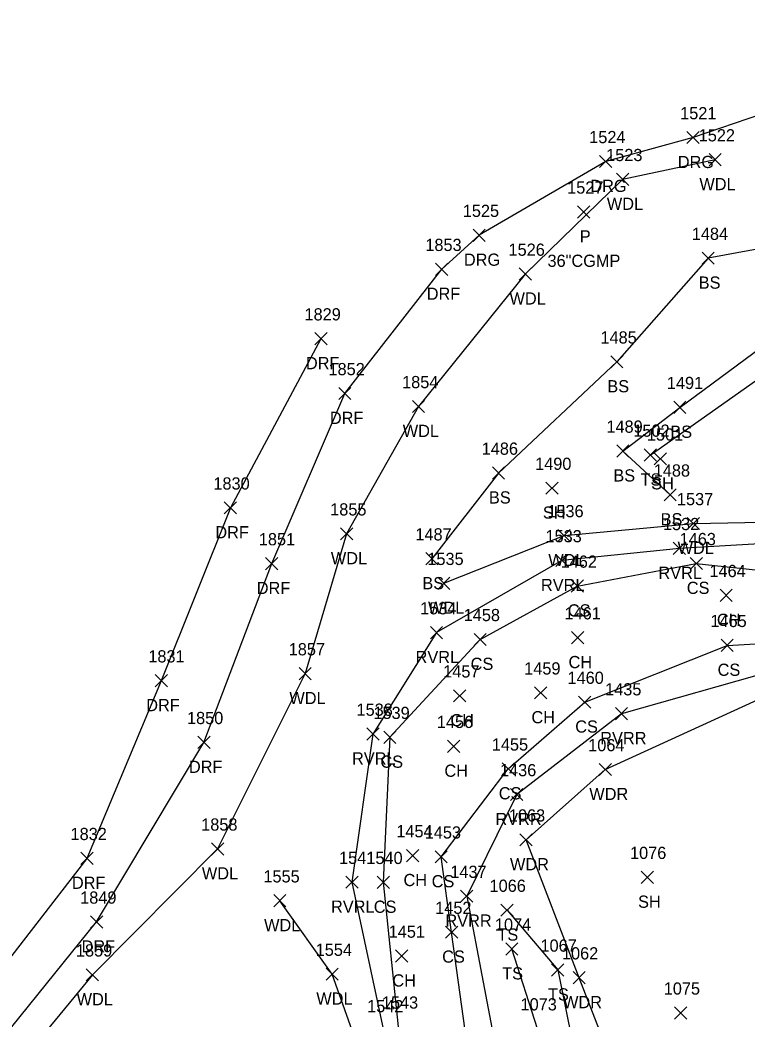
# Model space of a CAD drawing. Extents: x 1621633 to 1624015, y 417863 to 420979.
# Drawn here: x 1621891.2 to 1622010.4, y 418184 to 418348 of the extents above; entities that cross this region are included whole.
import ezdxf

# ---------------------------------------------------------------- set-up
doc = ezdxf.new("R2010")
doc.units = 0
for name, color, linetype in [('D_A', 7, 'Continuous'), ('D_C', 7, 'Continuous'), ('D_I', 7, 'Continuous'), ('D_TIC', 7, 'Continuous'), ('L_A', 7, 'Continuous'), ('L_I', 7, 'Continuous'), ('L_TIC', 7, 'Continuous'), ('LAWA', 7, 'Continuous'), ('LAWE', 7, 'Continuous'), ('LELB', 7, 'Continuous'), ('R_A', 7, 'Continuous'), ('R_I', 7, 'Continuous'), ('R_TIC', 7, 'Continuous'), ('RDF', 7, 'Continuous'), ('RDG', 7, 'Continuous')]:
    doc.layers.add(name, color=color, linetype=linetype)

msp = doc.modelspace()

# ---------------------------------------------------------------- linework, layer by layer
at = {"layer": 'D_TIC'}
for points in [[(1621982.65, 418315.5), (1621984.65, 418317.5)], [(1621984.65, 418315.5), (1621982.65, 418317.5)]]:
    msp.add_lwpolyline(points, dxfattribs=at)
at = {"layer": 'L_TIC'}
for points in [[(1622004.21, 418324.07), (1622006.21, 418326.07)], [(1622006.21, 418324.07), (1622004.21, 418326.07)], [(1621989.04, 418320.84), (1621991.04, 418322.84)], [(1621991.04, 418320.84), (1621989.04, 418322.84)], [(1622003.08, 418307.92), (1622005.08, 418309.92)], [(1622005.08, 418307.92), (1622003.08, 418309.92)], [(1621973.09, 418305.32), (1621975.09, 418307.32)], [(1621975.09, 418305.32), (1621973.09, 418307.32)], [(1621988.1, 418290.93), (1621990.1, 418292.93)], [(1621990.1, 418290.93), (1621988.1, 418292.93)], [(1621955.58, 418283.61), (1621957.58, 418285.61)], [(1621957.58, 418283.61), (1621955.58, 418285.61)], [(1621998.43, 418283.47), (1622000.43, 418285.47)], [(1622000.43, 418283.47), (1621998.43, 418285.47)], [(1621989.09, 418276.31), (1621991.09, 418278.31)], [(1621991.09, 418276.31), (1621989.09, 418278.31)], [(1621993.58, 418275.65), (1621995.58, 418277.65)], [(1621995.58, 418275.65), (1621993.58, 418277.65)], [(1621995.24, 418275.02), (1621997.24, 418277.02)], [(1621997.24, 418275.02), (1621995.24, 418277.02)], [(1621968.69, 418272.7), (1621970.69, 418274.7)], [(1621970.69, 418272.7), (1621968.69, 418274.7)], [(1621977.48, 418270.22), (1621979.48, 418272.22)], [(1621979.48, 418270.22), (1621977.48, 418272.22)], [(1621996.84, 418269.12), (1621998.84, 418271.12)], [(1621998.84, 418269.12), (1621996.84, 418271.12)], [(1622000.65, 418264.43), (1622002.65, 418266.43)], [(1622002.65, 418264.43), (1622000.65, 418266.43)], [(1621943.79, 418262.74), (1621945.79, 418264.74)], [(1621945.79, 418262.74), (1621943.79, 418264.74)], [(1621979.44, 418262.45), (1621981.44, 418264.45)], [(1621981.44, 418262.45), (1621979.44, 418264.45)], [(1621998.35, 418260.34), (1622000.35, 418262.34)], [(1622000.35, 418260.34), (1621998.35, 418262.34)], [(1621957.77, 418258.65), (1621959.77, 418260.65)], [(1621959.77, 418258.65), (1621957.77, 418260.65)], [(1621979.1, 418258.35), (1621981.1, 418260.35)], [(1621981.1, 418258.35), (1621979.1, 418260.35)], [(1622001.13, 418257.88), (1622003.13, 418259.88)], [(1622003.13, 418257.88), (1622001.13, 418259.88)], [(1621959.73, 418254.62), (1621961.73, 418256.62)], [(1621961.73, 418254.62), (1621959.73, 418256.62)], [(1621981.62, 418254.18), (1621983.62, 418256.18)], [(1621983.62, 418254.18), (1621981.62, 418256.18)], [(1622006.02, 418252.64), (1622008.02, 418254.64)], [(1622008.02, 418252.64), (1622006.02, 418254.64)], [(1621958.54, 418246.53), (1621960.54, 418248.53)], [(1621960.54, 418246.53), (1621958.54, 418248.53)], [(1621965.69, 418245.42), (1621967.69, 418247.42)], [(1621967.69, 418245.42), (1621965.69, 418247.42)], [(1621981.69, 418245.71), (1621983.69, 418247.71)], [(1621983.69, 418245.71), (1621981.69, 418247.71)], [(1622006.18, 418244.45), (1622008.18, 418246.45)], [(1622008.18, 418244.45), (1622006.18, 418246.45)], [(1621936.99, 418239.81), (1621938.99, 418241.81)], [(1621938.99, 418239.81), (1621936.99, 418241.81)], [(1621975.61, 418236.67), (1621977.61, 418238.67)], [(1621977.61, 418236.67), (1621975.61, 418238.67)], [(1621962.32, 418236.18), (1621964.32, 418238.18)], [(1621964.32, 418236.18), (1621962.32, 418238.18)], [(1621982.84, 418235.14), (1621984.84, 418237.14)], [(1621984.84, 418235.14), (1621982.84, 418237.14)], [(1621988.87, 418233.25), (1621990.87, 418235.25)], [(1621990.87, 418233.25), (1621988.87, 418235.25)], [(1621948.11, 418229.91), (1621950.11, 418231.91)], [(1621950.11, 418229.91), (1621948.11, 418231.91)], [(1621950.89, 418229.38), (1621952.89, 418231.38)], [(1621952.89, 418229.38), (1621950.89, 418231.38)], [(1621961.34, 418227.9), (1621963.34, 418229.9)], [(1621963.34, 418227.9), (1621961.34, 418229.9)], [(1621970.3, 418224.2), (1621972.3, 418226.2)], [(1621972.3, 418224.2), (1621970.3, 418226.2)], [(1621986.21, 418224.09), (1621988.21, 418226.09)], [(1621988.21, 418224.09), (1621986.21, 418226.09)], [(1621971.68, 418219.99), (1621973.68, 418221.99)], [(1621973.68, 418219.99), (1621971.68, 418221.99)], [(1621973.22, 418212.57), (1621975.22, 418214.57)], [(1621975.22, 418212.57), (1621973.22, 418214.57)], [(1621922.64, 418211.08), (1621924.64, 418213.08)], [(1621924.64, 418211.08), (1621922.64, 418213.08)], [(1621954.63, 418209.98), (1621956.63, 418211.98)], [(1621956.63, 418209.98), (1621954.63, 418211.98)], [(1621959.3, 418209.78), (1621961.3, 418211.78)], [(1621961.3, 418209.78), (1621959.3, 418211.78)], [(1621944.67, 418205.62), (1621946.67, 418207.62)], [(1621946.67, 418205.62), (1621944.67, 418207.62)], [(1621949.81, 418205.6), (1621951.81, 418207.6)], [(1621951.81, 418205.6), (1621949.81, 418207.6)], [(1621993.09, 418206.43), (1621995.09, 418208.43)], [(1621995.09, 418206.43), (1621993.09, 418208.43)], [(1621932.84, 418202.58), (1621934.84, 418204.58)], [(1621934.84, 418202.58), (1621932.84, 418204.58)], [(1621963.49, 418203.33), (1621965.49, 418205.33)], [(1621965.49, 418203.33), (1621963.49, 418205.33)], [(1621970.1, 418201.04), (1621972.1, 418203.04)], [(1621972.1, 418201.04), (1621970.1, 418203.04)], [(1621961.01, 418197.43), (1621963.01, 418199.43)], [(1621963.01, 418197.43), (1621961.01, 418199.43)], [(1621970.89, 418194.68), (1621972.89, 418196.68)], [(1621972.89, 418194.68), (1621970.89, 418196.68)], [(1621952.82, 418193.52), (1621954.82, 418195.52)], [(1621954.82, 418193.52), (1621952.82, 418195.52)], [(1621902.11, 418190.44), (1621904.11, 418192.44)], [(1621904.11, 418190.44), (1621902.11, 418192.44)], [(1621941.42, 418190.54), (1621943.42, 418192.54)], [(1621943.42, 418190.54), (1621941.42, 418192.54)], [(1621978.4, 418191.23), (1621980.4, 418193.23)], [(1621980.4, 418191.23), (1621978.4, 418193.23)], [(1621981.92, 418189.96), (1621983.92, 418191.96)], [(1621983.92, 418189.96), (1621981.92, 418191.96)], [(1621998.57, 418184.19), (1622000.57, 418186.19)], [(1622000.57, 418184.19), (1621998.57, 418186.19)]]:
    msp.add_lwpolyline(points, dxfattribs=at)
at = {"layer": 'LAWA'}
for points in [[(1622005.21, 418325.07), (1621990.04, 418321.84), (1621974.09, 418306.32)], [(1621974.09, 418306.32), (1621956.58, 418284.61)], [(1621956.58, 418284.61), (1621944.79, 418263.74), (1621937.99, 418240.81), (1621923.64, 418212.08), (1621903.11, 418191.44), (1621882.69, 418166.67), (1621873.44, 418154.29), (1621850.99, 418135.57), (1621826.17, 418116.06), (1621804.72, 418096.14), (1621776.82, 418074.39), (1621781.78, 418070.72), (1621808.71, 418078.7), (1621829.62, 418083.56), (1621862.33, 418091.33), (1621892.29, 418098.27), (1621914.93, 418102.81), (1621920.3, 418103.1), (1621927.79, 418103.9), (1621958.83, 418106.15)], [(1621960.73, 418255.62), (1621980.44, 418263.45), (1622001.65, 418265.43)], [(1622001.65, 418265.43), (1622021.3, 418265.82)], [(1622320.21, 418157.08), (1622282.22, 418156.15), (1622251.71, 418155.08), (1622223.6, 418155.09), (1622209.11, 418155.31), (1622180.88, 418152.89), (1622152.12, 418150.87), (1622117.37, 418144.74), (1622094.14, 418141.69), (1622062.96, 418134.28), (1622030.01, 418125.89), (1622002.09, 418113.22), (1622001.94, 418118.19), (1622004.41, 418142.61), (1621992.55, 418166.21), (1621982.92, 418190.96), (1621974.22, 418213.57), (1621987.21, 418225.09), (1622016.71, 418238.58), (1622052.18, 418242.59)], [(1621964.88, 418112.57), (1621960.51, 418127.09), (1621958.47, 418132.3), (1621952.2, 418163.99), (1621942.42, 418191.54), (1621933.84, 418203.58)]]:
    msp.add_lwpolyline(points, dxfattribs=at)
at = {"layer": 'LAWE'}
for points in [[(1622333.17, 418232.98), (1622304.92, 418224.43), (1622278.58, 418222.6), (1622250.59, 418234.06), (1622231.09, 418250.9), (1622207.09, 418257.63), (1622185.14, 418265.61), (1622157.85, 418271.29), (1622128.42, 418279.11), (1622109.18, 418281.03), (1622103.42, 418276.53), (1622081.07, 418269.59), (1622054.89, 418266.85), (1622024.68, 418262.78), (1621999.35, 418261.34), (1621980.1, 418259.35), (1621959.54, 418247.53), (1621949.11, 418230.91), (1621945.67, 418206.62), (1621950.84, 418182.3), (1621958.69, 418157.04), (1621962.92, 418133.77), (1621970.23, 418110.89)], [(1622323.31, 418180.93), (1622300.82, 418170.32), (1622276.31, 418168.44), (1622241.72, 418167.29), (1622221.82, 418173.51), (1622205.88, 418194.82), (1622185.97, 418220.63), (1622162.23, 418235.42), (1622129.82, 418241.7), (1622106.38, 418246.35), (1622101.43, 418250.25), (1622073.09, 418248.58), (1622043.82, 418244.16), (1622014.93, 418241.31), (1621989.87, 418234.25), (1621972.68, 418220.99), (1621964.49, 418204.33), (1621969.88, 418176.14), (1621978.91, 418154.62), (1621984.37, 418139.62), (1621989.94, 418122.86), (1621991.15, 418115.14)]]:
    msp.add_lwpolyline(points, dxfattribs=at)
at = {"layer": 'LELB'}
for points in [[(1622104.98, 418282.3), (1622095.2, 418294.25), (1622098.08, 418303.07), (1622082.32, 418316.41), (1622059.02, 418318.28), (1622035.86, 418314.76), (1622004.08, 418308.92), (1621989.1, 418291.93), (1621969.69, 418273.7), (1621958.77, 418259.65)], [(1621997.84, 418270.12), (1621990.09, 418277.31), (1621999.43, 418284.47), (1622018.11, 418298.26), (1622043.7, 418305.02), (1622071.43, 418306.95), (1622080.52, 418293.1), (1622093.77, 418281.88)], [(1621994.58, 418276.65), (1622013.68, 418290.12), (1622039.52, 418301.76), (1622066, 418303.22), (1622071.17, 418289.62)], [(1621966.69, 418246.42), (1621982.62, 418255.18), (1622002.13, 418258.88), (1622025.63, 418256.38), (1622052.08, 418261.91), (1622065.2, 418262.89), (1622087.25, 418265.4)], [(1621986.07, 418114.57), (1621980.01, 418135.51), (1621971.8, 418158.97), (1621964.78, 418178.35), (1621962.01, 418198.43), (1621960.3, 418210.78), (1621971.3, 418225.2), (1621983.84, 418236.14), (1622007.18, 418245.45), (1622025.65, 418246.51), (1622054.04, 418255.07), (1622065.32, 418256.15)], [(1621951.89, 418230.38), (1621966.69, 418246.42)], [(1621951.89, 418230.38), (1621950.81, 418206.6), (1621953.26, 418182.89), (1621961.47, 418157.62), (1621964.44, 418135.42), (1621972.58, 418110.48)], [(1621971.1, 418202.04), (1621979.4, 418192.23), (1621984.23, 418168.43), (1621996.45, 418147.46), (1621999.49, 418124.25), (1621994.98, 418134.3), (1621984.25, 418161.1), (1621976.08, 418182.6), (1621971.89, 418195.68)]]:
    msp.add_lwpolyline(points, dxfattribs=at)
at = {"layer": 'R_TIC'}
for points in [[(1622000.6, 418327.7), (1622002.6, 418329.7)], [(1622002.6, 418327.7), (1622000.6, 418329.7)], [(1621986.27, 418323.78), (1621988.27, 418325.78)], [(1621988.27, 418323.78), (1621986.27, 418325.78)], [(1621965.53, 418311.68), (1621967.53, 418313.68)], [(1621967.53, 418311.68), (1621965.53, 418313.68)], [(1621959.39, 418306.1), (1621961.39, 418308.1)], [(1621961.39, 418306.1), (1621959.39, 418308.1)], [(1621939.59, 418294.72), (1621941.59, 418296.72)], [(1621941.59, 418294.72), (1621939.59, 418296.72)], [(1621943.51, 418285.74), (1621945.51, 418287.74)], [(1621945.51, 418285.74), (1621943.51, 418287.74)], [(1621924.73, 418266.99), (1621926.73, 418268.99)], [(1621926.73, 418266.99), (1621924.73, 418268.99)], [(1621931.52, 418257.85), (1621933.52, 418259.85)], [(1621933.52, 418257.85), (1621931.52, 418259.85)], [(1621913.41, 418238.65), (1621915.41, 418240.65)], [(1621915.41, 418238.65), (1621913.41, 418240.65)], [(1621920.4, 418228.54), (1621922.4, 418230.54)], [(1621922.4, 418228.54), (1621920.4, 418230.54)], [(1621901.22, 418209.53), (1621903.22, 418211.53)], [(1621903.22, 418209.53), (1621901.22, 418211.53)], [(1621902.81, 418199.1), (1621904.81, 418201.1)], [(1621904.81, 418199.1), (1621902.81, 418201.1)]]:
    msp.add_lwpolyline(points, dxfattribs=at)
at = {"layer": 'RDF'}
for points in [[(1621960.39, 418307.1), (1621966.53, 418312.68)], [(1621776.02, 418061.68), (1621769.52, 418069.9), (1621769.16, 418078.76), (1621780.25, 418093.21), (1621805.38, 418110.92), (1621830.45, 418131.22), (1621857.04, 418151.01), (1621883.03, 418174.44), (1621903.81, 418200.1), (1621921.4, 418229.54), (1621932.52, 418258.85), (1621944.51, 418286.74), (1621960.39, 418307.1)], [(1621940.59, 418295.72), (1621925.73, 418267.99), (1621914.41, 418239.65), (1621902.22, 418210.53), (1621883.89, 418186.91), (1621861.02, 418166.16), (1621838.61, 418146.11), (1621813.95, 418127.94), (1621789.4, 418110.13), (1621762.83, 418096.6), (1621756.07, 418081.78), (1621758.54, 418055.77)]]:
    msp.add_lwpolyline(points, dxfattribs=at)
at = {"layer": 'RDG'}
msp.add_lwpolyline([(1622075.73, 418347.97), (1622049.16, 418344.23), (1622026.25, 418337.1), (1622001.6, 418328.7), (1621987.27, 418324.78), (1621966.53, 418312.68)], dxfattribs=at)

# ---------------------------------------------------------------- texts
at = {"layer": 'D_A'}
msp.add_text('P', height=2, dxfattribs=at).set_placement((1621983.02, 418311.5))
at = {"layer": 'D_C'}
msp.add_text('36"CGMP', height=2, dxfattribs=at).set_placement((1621977.73, 418307.5))
at = {"layer": 'D_I'}
msp.add_text('1527', height=2, dxfattribs=at).set_placement((1621980.95, 418319.5))
at = {"layer": 'L_A'}
for s, p in [('WDL', (1622002.63, 418320.07)), ('WDL', (1621987.46, 418316.84)), ('BS', (1622002.52, 418303.92)), ('WDL', (1621971.5, 418301.32)), ('BS', (1621987.54, 418286.93)), ('WDL', (1621954, 418279.61)), ('BS', (1621997.87, 418279.47)), ('BS', (1621988.53, 418272.31)), ('TS', (1621992.99, 418271.65)), ('SH', (1621994.73, 418271.02)), ('BS', (1621968.13, 418268.7)), ('SH', (1621976.97, 418266.22)), ('BS', (1621996.28, 418265.12)), ('WDL', (1621999.06, 418260.43)), ('WDL', (1621942.21, 418258.74)), ('WDL', (1621977.86, 418258.45)), ('RVRL', (1621995.92, 418256.34)), ('BS', (1621957.21, 418254.65)), ('RVRL', (1621976.66, 418254.35)), ('CS', (1622000.57, 418253.88)), ('WDL', (1621958.14, 418250.62)), ('CS', (1621981.07, 418250.18)), ('CH', (1622005.51, 418248.64)), ('RVRL', (1621956.11, 418242.53)), ('CS', (1621965.13, 418241.42)), ('CH', (1621981.18, 418241.71)), ('CS', (1622005.62, 418240.45)), ('WDL', (1621935.41, 418235.81)), ('CH', (1621961.81, 418232.18)), ('CH', (1621975.1, 418232.67)), ('CS', (1621982.28, 418231.14)), ('RVRR', (1621986.38, 418229.25)), ('RVRL', (1621945.68, 418225.91)), ('CS', (1621950.33, 418225.38)), ('CH', (1621960.83, 418223.9)), ('CS', (1621969.74, 418220.2)), ('WDR', (1621984.58, 418220.09)), ('RVRR', (1621969.2, 418215.99)), ('WDR', (1621971.58, 418208.57)), ('WDL', (1621921.06, 418207.08)), ('CH', (1621954.12, 418205.98)), ('CS', (1621958.74, 418205.78)), ('SH', (1621992.58, 418202.43)), ('RVRL', (1621942.24, 418201.62)), ('CS', (1621949.25, 418201.6)), ('RVRR', (1621961, 418199.33)), ('WDL', (1621931.26, 418198.58)), ('TS', (1621969.51, 418197.04)), ('CS', (1621960.46, 418193.43)), ('TS', (1621970.3, 418190.68)), ('CH', (1621952.3, 418189.52)), ('TS', (1621977.81, 418187.23)), ('WDL', (1621900.53, 418186.44)), ('WDL', (1621939.83, 418186.54)), ('WDR', (1621980.28, 418185.96))]:
    msp.add_text(s, height=2, dxfattribs=at).set_placement(p)
at = {"layer": 'L_I'}
for s, p in [('1522', (1622002.52, 418328.07)), ('1523', (1621987.35, 418324.84)), ('1484', (1622001.39, 418311.92)), ('1526', (1621971.34, 418309.32)), ('1485', (1621986.41, 418294.93)), ('1854', (1621953.89, 418287.61)), ('1491', (1621997.3, 418287.47)), ('1489', (1621987.39, 418280.31)), ('1502', (1621991.8, 418279.65)), ('1501', (1621994.03, 418279.02)), ('1486', (1621966.94, 418276.7)), ('1490', (1621975.7, 418274.22)), ('1488', (1621995.15, 418273.12)), ('1537', (1621998.95, 418268.43)), ('1855', (1621942.1, 418266.74)), ('1536', (1621977.7, 418266.45)), ('1532', (1621996.66, 418264.34)), ('1487', (1621956.07, 418262.65)), ('1533', (1621977.4, 418262.35)), ('1463', (1621999.39, 418261.88)), ('1535', (1621958.03, 418258.62)), ('1462', (1621979.88, 418258.18)), ('1464', (1622004.28, 418256.64)), ('1534', (1621956.85, 418250.53)), ('1458', (1621963.99, 418249.42)), ('1461', (1621980.52, 418249.71)), ('1465', (1622004.44, 418248.45)), ('1857', (1621935.3, 418243.81)), ('1457', (1621960.63, 418240.18)), ('1459', (1621973.91, 418240.67)), ('1460', (1621981.01, 418239.14)), ('1435', (1621987.18, 418237.25)), ('1538', (1621946.42, 418233.91)), ('1539', (1621949.19, 418233.38)), ('1456', (1621959.59, 418231.9)), ('1455', (1621968.6, 418228.2)), ('1064', (1621984.4, 418228.09)), ('1436', (1621969.94, 418223.99)), ('1858', (1621920.95, 418215.08)), ('1063', (1621971.4, 418216.57)), ('1454', (1621952.94, 418213.98)), ('1453', (1621957.6, 418213.78)), ('1076', (1621991.26, 418210.43)), ('1541', (1621943.55, 418209.62)), ('1540', (1621948.03, 418209.6)), ('1437', (1621961.8, 418207.33)), ('1555', (1621931.15, 418206.58)), ('1066', (1621968.23, 418205.04)), ('1452', (1621959.32, 418201.43)), ('1074', (1621969.11, 418198.68)), ('1451', (1621951.69, 418197.52)), ('1859', (1621900.41, 418194.44)), ('1554', (1621939.72, 418194.54)), ('1067', (1621976.58, 418195.23)), ('1062', (1621980.1, 418193.96)), ('1075', (1621996.79, 418188.19)), ('1543', (1621950.57, 418185.89)), ('1073', (1621973.31, 418185.6)), ('1542', (1621948.15, 418185.3))]:
    msp.add_text(s, height=2, dxfattribs=at).set_placement(p)
at = {"layer": 'R_A'}
for s, p in [('DRG', (1621999.09, 418323.7)), ('DRG', (1621984.76, 418319.78)), ('DRG', (1621964.02, 418307.68)), ('DRF', (1621957.93, 418302.1)), ('DRF', (1621938.12, 418290.72)), ('DRF', (1621942.05, 418281.74)), ('DRF', (1621923.27, 418262.99)), ('DRF', (1621930.06, 418253.85)), ('DRF', (1621911.94, 418234.65)), ('DRF', (1621918.94, 418224.54)), ('DRF', (1621899.75, 418205.53)), ('DRF', (1621901.34, 418195.1))]:
    msp.add_text(s, height=2, dxfattribs=at).set_placement(p)
at = {"layer": 'R_I'}
for s, p in [('1521', (1621999.48, 418331.7)), ('1524', (1621984.57, 418327.78)), ('1525', (1621963.84, 418315.68)), ('1853', (1621957.7, 418310.1)), ('1829', (1621937.89, 418298.72)), ('1852', (1621941.82, 418289.74)), ('1830', (1621922.95, 418270.99)), ('1851', (1621930.4, 418261.85)), ('1831', (1621912.28, 418242.65)), ('1850', (1621918.62, 418232.54)), ('1832', (1621899.53, 418213.53)), ('1849', (1621901.11, 418203.1))]:
    msp.add_text(s, height=2, dxfattribs=at).set_placement(p)

doc.saveas('drawing.dxf')
